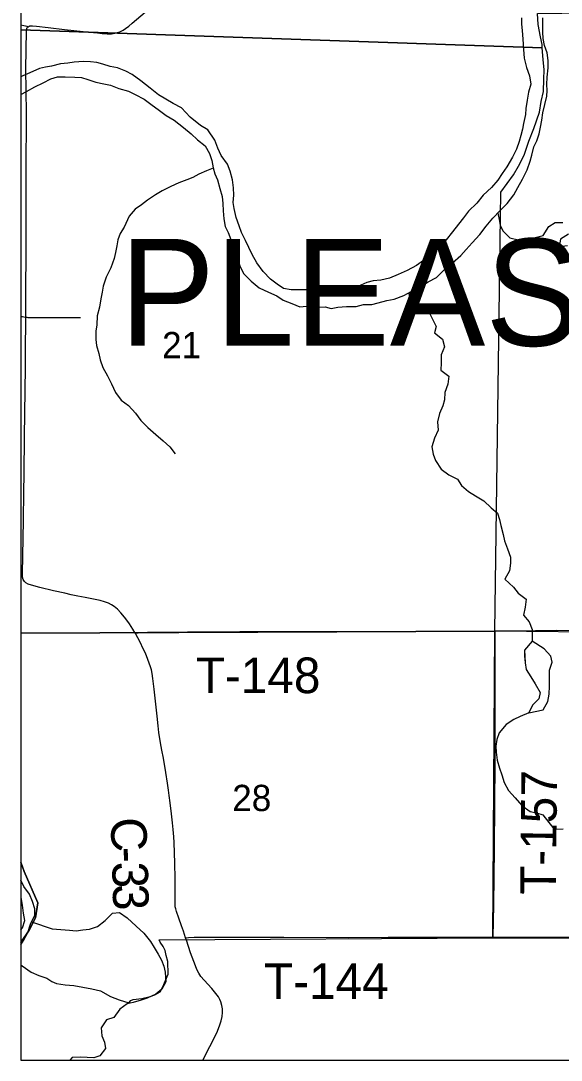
# Model space of a CAD drawing. Extents: x -8.5 to 18.7, y -20.3 to 7.
# Drawn here: x -8.459 to -6.737, y -20.262 to -16.948 of the extents above; entities that cross this region are included whole.
import ezdxf

# ---------------------------------------------------------------- set-up
doc = ezdxf.new("R2010")
doc.units = 0
for name, color, linetype in [('GM_X_Corporation', 7, 'Continuous'), ('GM_X_County_Road', 7, 'Continuous'), ('GM_X_County_Road_Text', 7, 'Continuous'), ('GM_X_Major_River', 7, 'Continuous'), ('GM_X_Minor_Lake', 7, 'Continuous'), ('GM_X_Minor_River', 7, 'Continuous'), ('GM_X_Section', 7, 'Continuous'), ('GM_X_Section_Text', 7, 'Continuous'), ('GM_X_Township_Road', 7, 'Continuous'), ('GM_X_Township_Road_Text', 7, 'Continuous'), ('GM_X_Township_Text', 7, 'Continuous'), ('GM_X_Unincorporated_Text', 7, 'Continuous'), ('SH_Cut_Line', 7, 'Continuous')]:
    doc.layers.add(name, color=color, linetype=linetype)

msp = doc.modelspace()

# ---------------------------------------------------------------- linework, layer by layer
at = {"layer": 'GM_X_Corporation'}
msp.add_lwpolyline([(-8.4587, -10.6981), (-8.4587, -20.262), (-0.9232, -20.262)], dxfattribs=at)
at = {"layer": 'GM_X_County_Road'}
for points in [[(-8.4351, -16.9664), (-8.4316, -16.9647), (-8.4297, -16.9642), (-8.4277, -16.9638), (-8.4212, -16.9636), (-8.4085, -16.9645), (-8.372, -16.9692), (-8.3197, -16.9751), (-8.24, -16.9836), (-8.214, -16.9863), (-8.1992, -16.9878), (-8.1832, -16.989), (-8.1698, -16.9887), (-8.1589, -16.9871), (-8.1506, -16.9852), (-8.1427, -16.9824), (-8.1329, -16.9773), (-8.1247, -16.9721), (-8.1149, -16.9647), (-8.1034, -16.9552), (-8.0628, -16.9204)], [(-8.442, -17.4947), (-8.442, -17.4327), (-8.4408, -17.2413), (-8.4425, -17.1008), (-8.4408, -16.9801), (-8.4405, -16.9767), (-8.4399, -16.9736), (-8.4392, -16.9715), (-8.4381, -16.9698), (-8.4369, -16.9681), (-8.4351, -16.9664)], [(-8.4431, -17.8923), (-8.4431, -17.8365), (-8.4419, -17.6588), (-8.442, -17.4947)], [(-8.0939, -18.9004), (-8.1021, -18.8873), (-8.1126, -18.8709), (-8.121, -18.8591), (-8.128, -18.8495), (-8.1398, -18.8353), (-8.1509, -18.8238), (-8.1612, -18.8151), (-8.1693, -18.8097), (-8.1791, -18.8047), (-8.1917, -18.8003), (-8.206, -18.7965), (-8.2327, -18.7908), (-8.2537, -18.7868), (-8.2771, -18.7824), (-8.2977, -18.7779), (-8.3189, -18.7732), (-8.3548, -18.765), (-8.3982, -18.7545), (-8.4248, -18.7475), (-8.4356, -18.7437), (-8.4424, -18.7397), (-8.4472, -18.7352), (-8.4507, -18.7296), (-8.4528, -18.7219), (-8.4532, -18.7104), (-8.4501, -18.5414), (-8.449, -18.4494), (-8.4484, -18.3935), (-8.4464, -18.2729), (-8.4438, -18.0529), (-8.4433, -18.0068), (-8.4431, -17.8923)], [(-7.9335, -19.8716), (-7.9408, -19.8509), (-7.9469, -19.8336), (-7.9556, -19.809), (-7.9627, -19.7877), (-7.965, -19.7795), (-7.9663, -19.7726), (-7.967, -19.7647), (-7.967, -19.6824), (-7.9674, -19.634), (-7.9695, -19.5682), (-7.9706, -19.5498), (-7.9727, -19.5266), (-7.9748, -19.5052), (-7.9781, -19.4768), (-7.9829, -19.4411), (-7.9862, -19.4177), (-7.9885, -19.4005), (-7.9915, -19.3783), (-7.9961, -19.3451), (-8.0043, -19.2987), (-8.0091, -19.2736), (-8.0136, -19.2499), (-8.0188, -19.2168), (-8.0212, -19.1958), (-8.0238, -19.1649), (-8.029, -19.1167), (-8.0333, -19.0784), (-8.0376, -19.0449), (-8.0399, -19.0288), (-8.0425, -19.0176), (-8.0455, -19.0074), (-8.0495, -18.9962), (-8.0534, -18.9847), (-8.0583, -18.9731), (-8.0626, -18.9623), (-8.0683, -18.9504), (-8.0787, -18.9293), (-8.093, -18.9018), (-8.0939, -18.9004)], [(-7.879, -20.262), (-7.8345, -20.1742), (-7.8258, -20.1523), (-7.8204, -20.136), (-7.8173, -20.1229), (-7.816, -20.1095), (-7.8161, -20.0986), (-7.8177, -20.0877), (-7.8209, -20.076), (-7.8243, -20.0683), (-7.8291, -20.0598), (-7.8369, -20.0488), (-7.8498, -20.0338), (-7.8743, -20.0073), (-7.8847, -19.9947), (-7.8917, -19.9842), (-7.8975, -19.9731), (-7.9024, -19.9615), (-7.9176, -19.9193), (-7.9243, -19.8993), (-7.9309, -19.8792), (-7.9335, -19.8716)]]:
    msp.add_lwpolyline(points, dxfattribs=at)
at = {"layer": 'GM_X_Major_River'}
for points in [[(-6.8634, -16.9381), (-6.8636, -16.9579), (-6.8607, -16.9784), (-6.8593, -17.0065), (-6.8572, -17.0392), (-6.8544, -17.0673), (-6.8478, -17.0969), (-6.8381, -17.1236), (-6.8337, -17.1502), (-6.8407, -17.1752), (-6.8454, -17.201), (-6.8493, -17.2268), (-6.8502, -17.2465), (-6.8565, -17.2746), (-6.8604, -17.2935), (-6.8658, -17.3132), (-6.8712, -17.3322), (-6.8797, -17.3572), (-6.892, -17.3829), (-6.9096, -17.4132), (-6.9249, -17.4344), (-6.9387, -17.4563), (-6.9585, -17.4797), (-6.9852, -17.5039), (-7.0058, -17.5296)], [(-6.9546, -17.577), (-6.9309, -17.5528), (-6.9088, -17.5302), (-6.8882, -17.5029), (-6.8752, -17.4787), (-6.8606, -17.453), (-6.8453, -17.4227), (-6.836, -17.3954), (-6.8306, -17.3765), (-6.8236, -17.3499), (-6.8144, -17.3302), (-6.8067, -17.3083), (-6.8027, -17.2863), (-6.7981, -17.265), (-6.7956, -17.2408), (-6.7894, -17.2142), (-6.7824, -17.1884), (-6.7815, -17.1695), (-6.7822, -17.1505), (-6.782, -17.1269), (-6.7788, -17.0973), (-6.7787, -17.0746), (-6.7816, -17.0495), (-6.7897, -17.0267), (-6.7941, -17.0039), (-6.7955, -16.9841), (-6.7953, -16.9385)], [(-7.0058, -17.5296), (-7.0325, -17.5545), (-7.0485, -17.5757), (-7.0638, -17.5961), (-7.0836, -17.6202), (-7.1035, -17.6459), (-7.1272, -17.6724), (-7.1493, -17.6958), (-7.1751, -17.7123), (-7.198, -17.7274), (-7.2276, -17.7439), (-7.2565, -17.7567), (-7.2838, -17.7679), (-7.3111, -17.7746), (-7.3362, -17.7767), (-7.3566, -17.7819), (-7.3756, -17.7901), (-7.4022, -17.8029), (-7.425, -17.8103), (-7.4508, -17.8147), (-7.4773, -17.8138), (-7.5038, -17.8053), (-7.5507, -17.805), (-7.5773, -17.8056), (-7.597, -17.8055), (-7.6212, -17.8008), (-7.6415, -17.787), (-7.6627, -17.7717), (-7.6868, -17.7473), (-7.7063, -17.7191), (-7.722, -17.6924), (-7.7317, -17.6703), (-7.7422, -17.6482), (-7.7557, -17.6231), (-7.7631, -17.6018), (-7.7728, -17.5752), (-7.7787, -17.5463), (-7.7816, -17.5273), (-7.7799, -17.5038), (-7.7805, -17.4802), (-7.7842, -17.4551), (-7.7916, -17.427), (-7.8005, -17.4049), (-7.82, -17.3775), (-7.8313, -17.3539), (-7.8409, -17.328), (-7.8627, -17.2952), (-7.8861, -17.2814), (-7.9185, -17.2546), (-7.9464, -17.2249), (-7.9728, -17.211), (-7.9962, -17.198), (-8.0204, -17.1842), (-8.0467, -17.162), (-8.0761, -17.139), (-8.1041, -17.1191), (-8.1244, -17.1084), (-8.1509, -17.0976), (-8.1736, -17.0929), (-8.197, -17.0859), (-8.2167, -17.0805), (-8.2371, -17.0789), (-8.2591, -17.0772), (-8.2887, -17.0793), (-8.3084, -17.0822), (-8.3319, -17.0851), (-8.3607, -17.0918), (-8.3804, -17.0955), (-8.3994, -17.0992), (-8.4298, -17.1134), (-8.4518, -17.1232), (-8.4587, -17.1267)], [(-8.4587, -17.1821), (-8.4408, -17.1726), (-8.4142, -17.1583), (-8.3876, -17.1456), (-8.3632, -17.1328), (-8.342, -17.1268), (-8.317, -17.1262), (-8.2867, -17.1272), (-8.2655, -17.1288), (-8.2451, -17.1343), (-8.2194, -17.1428), (-8.1944, -17.1482), (-8.1732, -17.1529), (-8.1468, -17.1637), (-8.115, -17.1722), (-8.0946, -17.1822), (-8.0659, -17.1976), (-8.0403, -17.2167), (-8.0207, -17.2305), (-7.995, -17.2496), (-7.9701, -17.2642), (-7.9407, -17.2879), (-7.9158, -17.3078), (-7.8955, -17.3277), (-7.8714, -17.346), (-7.8571, -17.3712), (-7.8497, -17.3932), (-7.8461, -17.4168), (-7.8409, -17.4358), (-7.8319, -17.4549), (-7.8245, -17.4822), (-7.8171, -17.5081), (-7.8149, -17.5301), (-7.8143, -17.5537), (-7.8122, -17.5787), (-7.8078, -17.6031), (-7.7981, -17.6229), (-7.7899, -17.6449), (-7.784, -17.6639), (-7.7758, -17.6853), (-7.7683, -17.7066), (-7.7609, -17.7294), (-7.7489, -17.753), (-7.7248, -17.7782), (-7.6992, -17.7988), (-7.6697, -17.8134), (-7.6433, -17.8242), (-7.6222, -17.838), (-7.595, -17.8496), (-7.5693, -17.8596), (-7.5382, -17.8567), (-7.5185, -17.8607), (-7.489, -17.8601), (-7.4693, -17.8647), (-7.4488, -17.8611), (-7.4208, -17.8582), (-7.3905, -17.8584), (-7.3669, -17.8524), (-7.3404, -17.8518), (-7.3199, -17.8466), (-7.2919, -17.8392), (-7.2691, -17.8348), (-7.2387, -17.8236), (-7.2144, -17.8108), (-7.1878, -17.7981), (-7.1604, -17.78), (-7.1338, -17.7657), (-7.1071, -17.7401), (-7.0835, -17.719), (-7.0561, -17.6963), (-7.0401, -17.6767), (-7.0202, -17.6555), (-6.9958, -17.6291), (-6.9759, -17.6027), (-6.9546, -17.577)], [(-8.4587, -19.8939), (-8.4496, -19.88), (-8.4366, -19.855), (-8.4273, -19.8277), (-8.4135, -19.7997), (-8.4141, -19.7792), (-8.4216, -19.7556), (-8.4313, -19.7321), (-8.4493, -19.7077), (-8.4587, -19.6879)], [(-8.4587, -19.8464), (-8.4532, -19.8397), (-8.4454, -19.8162), (-8.4498, -19.7927), (-8.4535, -19.7676), (-8.4578, -19.7418), (-8.4587, -19.741)]]:
    msp.add_lwpolyline(points, dxfattribs=at)
at = {"layer": 'GM_X_Minor_Lake'}
for points in [[(-6.829, -18.9262), (-6.8542, -18.9541), (-6.8514, -18.9951), (-6.8485, -19.0164), (-6.8335, -19.0393), (-6.82, -19.0621), (-6.8035, -19.0895), (-6.8082, -19.1093), (-6.8281, -19.1304), (-6.8403, -19.1546)], [(-6.8403, -19.1546), (-6.7941, -19.1443), (-6.7795, -19.1185), (-6.7748, -19.095), (-6.7739, -19.0692), (-6.7737, -19.0457), (-6.7743, -19.0184), (-6.7658, -18.9926), (-6.7702, -18.9736), (-6.7913, -18.9507), (-6.829, -18.9262)]]:
    msp.add_lwpolyline(points, dxfattribs=at)
at = {"layer": 'GM_X_Minor_River'}
for points in [[(-7.8458, -17.4178), (-7.8666, -17.4258), (-7.8916, -17.437), (-7.9106, -17.4476), (-7.9296, -17.455), (-7.9547, -17.4648), (-7.9805, -17.476), (-8.0079, -17.4903), (-8.0299, -17.503), (-8.055, -17.5196), (-8.0741, -17.5347), (-8.0939, -17.5482), (-8.1129, -17.5709), (-8.1298, -17.6057), (-8.1421, -17.6261), (-8.149, -17.6458), (-8.1522, -17.6656), (-8.1569, -17.686), (-8.1615, -17.7058), (-8.1716, -17.7353), (-8.1869, -17.7648), (-8.1962, -17.7936), (-8.1993, -17.8134), (-8.2032, -17.8338), (-8.208, -17.8604), (-8.215, -17.8884), (-8.2167, -17.9173), (-8.2191, -17.9378), (-8.2192, -17.9636), (-8.2178, -17.9826), (-8.2097, -18.0084), (-8.206, -18.0282), (-8.1978, -18.0533), (-8.1828, -18.0792), (-8.1701, -18.1051), (-8.1574, -18.1325), (-8.1386, -18.1569), (-8.116, -18.1745), (-8.0927, -18.1989), (-8.0761, -18.2218), (-8.0543, -18.2447), (-8.0279, -18.2669), (-8.0053, -18.2875), (-7.9835, -18.3059), (-7.967, -18.3288)], [(-6.9388, -17.5608), (-6.9349, -17.5809), (-6.9312, -17.5999), (-6.9215, -17.6189), (-6.9004, -17.6395), (-6.8739, -17.6458), (-6.8474, -17.6437), (-6.8193, -17.6385), (-6.7943, -17.6318), (-6.7767, -17.6038), (-6.7562, -17.591), (-6.7312, -17.5912)], [(-6.7132, -17.6285), (-6.7391, -17.6435), (-6.743, -17.6671), (-6.7165, -17.6642)], [(-7.2226, -17.8151), (-7.2198, -17.8328), (-7.201, -17.8542), (-7.1806, -17.8604), (-7.1587, -17.8757), (-7.1483, -17.897), (-7.1348, -17.9229), (-7.1402, -17.9426), (-7.1154, -17.9633), (-7.1087, -17.9876), (-7.1194, -18.0126), (-7.1189, -18.0384), (-7.1205, -18.0619), (-7.0949, -18.0803), (-7.0981, -18.1061), (-7.1073, -18.1326), (-7.1082, -18.1562), (-7.1137, -18.1751), (-7.1244, -18.2001), (-7.1314, -18.2266), (-7.1285, -18.2532), (-7.1401, -18.2782), (-7.1486, -18.3063), (-7.1449, -18.3298), (-7.1375, -18.3496), (-7.1195, -18.3778), (-7.0946, -18.3954), (-7.0674, -18.4092), (-7.0547, -18.4298), (-7.0321, -18.4489), (-7.0102, -18.4627), (-6.9838, -18.4788), (-6.9604, -18.501), (-6.9401, -18.5178), (-6.9334, -18.5383), (-6.9289, -18.5574), (-6.9216, -18.5855), (-6.9179, -18.606), (-6.9074, -18.6311), (-6.8985, -18.6578), (-6.8979, -18.6775), (-6.9011, -18.7018), (-6.9164, -18.7283), (-6.8893, -18.7535), (-6.8735, -18.7725), (-6.8479, -18.7917), (-6.8518, -18.8175), (-6.8573, -18.8425), (-6.8385, -18.8646), (-6.8295, -18.8882), (-6.8289, -18.9072), (-6.829, -18.9262), (-6.8542, -18.9541), (-6.8536, -18.9739), (-6.8514, -18.9951), (-6.8485, -19.0164), (-6.8335, -19.0393), (-6.82, -19.0621), (-6.8035, -19.0895), (-6.8082, -19.1093), (-6.8281, -19.1304), (-6.8403, -19.1546), (-6.8677, -19.1658), (-6.8882, -19.1756), (-6.9118, -19.1914), (-6.9347, -19.2186), (-6.9424, -19.239), (-6.9456, -19.261), (-6.9442, -19.28), (-6.9405, -19.3051), (-6.9331, -19.331), (-6.9257, -19.3515), (-6.919, -19.3766), (-6.9048, -19.4025), (-6.883, -19.4254), (-6.8619, -19.4498), (-6.8355, -19.4689), (-6.8159, -19.4736), (-6.7954, -19.4798), (-6.7759, -19.5042), (-6.7594, -19.5248), (-6.7306, -19.5242)], [(-8.4241, -19.8212), (-8.359, -19.8433), (-8.304, -19.8474), (-8.282, -19.8491), (-8.2608, -19.8462), (-8.2403, -19.844), (-8.2145, -19.8358), (-8.1894, -19.8162), (-8.1665, -19.7928), (-8.1445, -19.7907), (-8.1196, -19.8083), (-8.091, -19.8343), (-8.0669, -19.8572), (-8.0451, -19.8831), (-8.0339, -19.9022), (-8.0211, -19.9235), (-8.0106, -19.9425), (-8.0032, -19.9623), (-7.9988, -19.9813), (-7.9967, -20.0125), (-8.0089, -20.0352), (-8.028, -20.051), (-8.0561, -20.0645), (-8.0751, -20.0705), (-8.1009, -20.0779), (-8.1199, -20.0823), (-8.1427, -20.0997), (-8.1618, -20.1254), (-8.1861, -20.1328), (-8.2029, -20.1585), (-8.2001, -20.1844), (-8.1919, -20.2041), (-8.189, -20.2247), (-8.2073, -20.2481), (-8.2263, -20.254), (-8.2687, -20.2523), (-8.2945, -20.2529), (-8.3022, -20.262)]]:
    msp.add_lwpolyline(points, dxfattribs=at)
at = {"layer": 'GM_X_Section'}
msp.add_lwpolyline([(-6.8119, -16.9248), (-4.8803, -16.8978), (-4.9245, -18.9152), (-6.9481, -18.8937), (-6.9297, -17.5727), (-6.9291, -17.4939), (-6.8886, -17.439), (-6.873, -17.4115), (-6.8551, -17.3757), (-6.8396, -17.3316), (-6.8241, -17.291), (-6.8062, -17.2385), (-6.8002, -17.2051), (-6.7931, -17.1728), (-6.7919, -17.1335), (-6.7907, -17.1036), (-6.7943, -17.0714), (-6.7971, -17.0342), (-6.7978, -17.0237), (-6.8026, -16.9986), (-6.8098, -16.9592)], close=True, dxfattribs=at)
at = {"layer": 'GM_X_Township_Road'}
for points in [[(-8.4587, -16.9606), (-8.4493, -16.9623), (-8.4436, -16.9636), (-8.4393, -16.965), (-8.4351, -16.9664)], [(-8.4587, -17.8902), (-8.4566, -17.8903), (-8.453, -17.8905), (-8.4492, -17.8911), (-8.4431, -17.8923)], [(-8.4431, -17.8923), (-8.4397, -17.8931), (-8.4358, -17.8937), (-8.4312, -17.8941), (-8.4128, -17.8941), (-8.372, -17.8941), (-8.3372, -17.8942), (-8.2989, -17.8942), (-8.268, -17.8942)], [(-6.947, -18.8929), (-6.8875, -18.8924), (-6.7508, -18.891), (-6.6515, -18.8924)], [(-8.0939, -18.9004), (-8.0844, -18.8992), (-8.0702, -18.8977), (-8.0553, -18.8968), (-7.9271, -18.8961), (-7.7607, -18.8952), (-7.6501, -18.895), (-7.4574, -18.8953), (-7.2672, -18.8948), (-7.0993, -18.8944), (-6.947, -18.8929)], [(-6.9538, -19.8699), (-6.9515, -19.767), (-6.9495, -19.5881), (-6.948, -19.4453), (-6.9476, -19.3149), (-6.9477, -19.1857), (-6.9475, -18.9646), (-6.947, -18.8953), (-6.947, -18.8929)], [(-7.9335, -19.8716), (-7.9239, -19.8705), (-7.9061, -19.8695), (-7.8564, -19.8695), (-7.7246, -19.8694), (-7.6202, -19.8699), (-7.4139, -19.8708), (-7.2883, -19.8702), (-7.2212, -19.8698), (-7.1342, -19.87), (-6.9538, -19.8699)], [(-6.9538, -19.8699), (-6.9042, -19.8698), (-6.8011, -19.8701), (-6.7352, -19.8696), (-6.678, -19.8702), (-6.6658, -19.8709), (-6.6577, -19.8719), (-6.6488, -19.8733), (-6.6333, -19.8773), (-6.6198, -19.882), (-6.6042, -19.8879), (-6.5965, -19.8909), (-6.584, -19.8945), (-6.5715, -19.8972), (-6.5566, -19.8988), (-6.5404, -19.8998), (-6.4906, -19.9003), (-6.3862, -19.9022), (-6.1364, -19.9051), (-5.7871, -19.9098), (-5.6118, -19.912), (-5.5172, -19.9132)]]:
    msp.add_lwpolyline(points, dxfattribs=at)
at = {"layer": 'GM_X_Unincorporated_Text'}
msp.add_lwpolyline([(-8.4587, -14.9031), (-8.4587, -16.9765), (-6.7971, -17.0342), (-6.7978, -17.0237), (-6.8026, -16.9986), (-6.8098, -16.9592), (-6.8119, -16.9248)], dxfattribs=at)
for points in [[(-8.4587, -16.9765), (-8.4587, -18.8999), (-6.9481, -18.8937), (-6.9297, -17.5727), (-6.9291, -17.4939), (-6.8886, -17.439), (-6.873, -17.4115), (-6.8551, -17.3757), (-6.8396, -17.3316), (-6.8241, -17.291), (-6.8062, -17.2385), (-6.8002, -17.2051), (-6.7931, -17.1728), (-6.7919, -17.1335), (-6.7907, -17.1036), (-6.7943, -17.0714), (-6.7971, -17.0342)], [(-8.4587, -19.887), (-8.4587, -19.9576), (-8.4539, -19.9608), (-8.4252, -19.9815), (-8.401, -19.9923), (-8.3761, -20.0008), (-8.3595, -20.0115), (-8.3451, -20.0169), (-8.3171, -20.0217), (-8.2899, -20.0242), (-8.2323, -20.0345), (-8.2044, -20.0408), (-8.1734, -20.0584), (-8.1454, -20.07), (-8.1144, -20.0786), (-8.1083, -20.0718), (-8.1007, -20.0681), (-8.0727, -20.0653), (-8.0468, -20.0586), (-8.0316, -20.0534), (-8.0149, -20.0437), (-8.0057, -20.0279), (-7.9887, -19.9878), (-7.9907, -19.9476), (-7.9951, -19.9279), (-7.9987, -19.912), (-8.0047, -19.899), (-8.0144, -19.8853), (-8.0174, -19.8777), (-6.9548, -19.8714), (-6.9481, -18.8937), (-8.4587, -18.8999), (-8.4587, -19.6307), (-8.4481, -19.6599), (-8.4046, -19.7607), (-8.4116, -19.8077), (-8.4324, -19.8477)], [(-6.6192, -20.262), (-4.9384, -20.262), (-4.9245, -18.9152), (-6.9481, -18.8937), (-6.9548, -19.8714), (-6.6196, -19.8729)], [(-8.4587, -19.6307), (-8.4587, -19.887), (-8.4324, -19.8477), (-8.4116, -19.8077), (-8.4046, -19.7607), (-8.4481, -19.6599)]]:
    msp.add_lwpolyline(points, close=True, dxfattribs=at)
at = {"layer": 'SH_Cut_Line'}
msp.add_lwpolyline([(-8.4587, -10.6981), (-8.4587, -20.262), (18.7413, -20.262), (18.7413, -10.9039)], dxfattribs=at)

# ---------------------------------------------------------------- texts
at = {"layer": 'GM_X_County_Road_Text'}
for s, rotation, p in [('C', 273.7144, (-8.1744, -19.4911)), ('-', 271.3193, (-8.1684, -19.583)), ('3', 270.7962, (-8.1673, -19.6294)), ('3', 271.7827, (-8.1663, -19.7015))]:
    msp.add_text(s, height=0.1136, rotation=rotation, dxfattribs=at).set_placement(p)
at = {"layer": 'GM_X_Section_Text'}
for s, p in [('21', (-8.0085, -18.0236)), ('28', (-7.7851, -19.4676))]:
    msp.add_text(s, height=0.08371, rotation=0, dxfattribs=at).set_placement(p)
at = {"layer": 'GM_X_Township_Road_Text'}
for s, rotation, p in [('T-148', 0, (-7.901, -19.0916)), ('T-157', 89.4383, (-6.7538, -19.7349)), ('T-144', 0.0063, (-7.6837, -20.0666))]:
    msp.add_text(s, height=0.11364, rotation=rotation, dxfattribs=at).set_placement(p)
at = {"layer": 'GM_X_Township_Text'}
msp.add_text('PLEASANT', height=0.34091, rotation=0, dxfattribs=at).set_placement((-8.1444, -17.9838))

doc.saveas('drawing.dxf')
